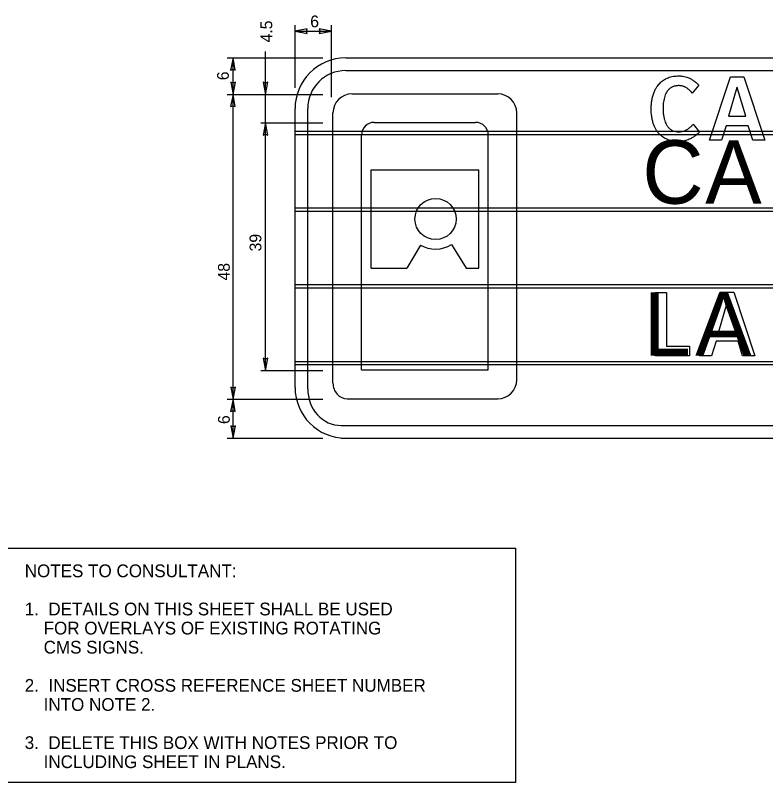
# Model space of a CAD drawing. Extents: x 319706 to 320346, y 1621790 to 1622121.
# Drawn here: x 319856.4 to 319945.5, y 1621813.2 to 1621904.4 of the extents above; entities that cross this region are included whole.
import ezdxf

# ---------------------------------------------------------------- set-up
doc = ezdxf.new("R2010")
doc.units = 0
for name, color, linetype in [('1', 7, 'Continuous'), ('52', 7, 'Continuous'), ('GSBWFill', 7, 'Continuous'), ('GSColorFill', 7, 'Continuous'), ('GSOutline', 7, 'Continuous'), ('SignPanel', 7, 'Continuous'), ('TextAlert', 7, 'Continuous')]:
    doc.layers.add(name, color=color, linetype=linetype)

msp = doc.modelspace()

# ---------------------------------------------------------------- linework, layer by layer
at = {"layer": '1'}
for p, q in [((319889.623, 1621895.788), (319889.623, 1621903.248)), ((319893.952, 1621894.663), (319893.952, 1621903.248)), ((319889.623, 1621902.519), (319893.952, 1621902.519)), ((319886.119, 1621895.01), (319886.119, 1621900.114)), ((319881.557, 1621899.343), (319892.941, 1621899.343)), ((319882.254, 1621895.01), (319882.254, 1621899.343)), ((319881.557, 1621895.01), (319892.941, 1621895.01)), ((319882.254, 1621858.786), (319882.254, 1621895.01)), ((319886.119, 1621891.622), (319886.119, 1621895.01)), ((319885.56, 1621891.622), (319892.941, 1621891.622)), ((319886.119, 1621862.212), (319886.119, 1621891.622)), ((319885.56, 1621862.212), (319892.941, 1621862.212)), ((319881.557, 1621858.786), (319892.941, 1621858.786)), ((319882.254, 1621854.168), (319882.254, 1621858.786)), ((319881.557, 1621854.168), (319892.941, 1621854.168))]:
    msp.add_line(p, q, dxfattribs=at)
at = {"layer": '52'}
for p, q in [((319891.073, 1621902.789), (319889.623, 1621902.519)), ((319889.623, 1621902.519), (319891.073, 1621902.239)), ((319890.963, 1621902.519), (319891.073, 1621902.789)), ((319891.073, 1621902.239), (319890.963, 1621902.519)), ((319893.952, 1621902.519), (319892.502, 1621902.799)), ((319892.502, 1621902.799), (319892.612, 1621902.519)), ((319892.612, 1621902.519), (319892.502, 1621902.249)), ((319892.502, 1621902.249), (319893.952, 1621902.519)), ((319882.254, 1621899.343), (319881.974, 1621897.893)), ((319882.524, 1621897.893), (319882.254, 1621899.343)), ((319881.974, 1621897.893), (319882.254, 1621898.003)), ((319882.254, 1621898.003), (319882.524, 1621897.893)), ((319882.254, 1621896.35), (319881.984, 1621896.46)), ((319881.984, 1621896.46), (319882.254, 1621895.01)), ((319882.254, 1621895.01), (319882.534, 1621896.46)), ((319882.534, 1621896.46), (319882.254, 1621896.35)), ((319886.119, 1621896.35), (319885.849, 1621896.46)), ((319885.849, 1621896.46), (319886.119, 1621895.01)), ((319886.119, 1621895.01), (319886.399, 1621896.46)), ((319886.399, 1621896.46), (319886.119, 1621896.35)), ((319882.254, 1621895.01), (319881.974, 1621893.56)), ((319882.524, 1621893.56), (319882.254, 1621895.01)), ((319881.974, 1621893.56), (319882.254, 1621893.67)), ((319882.254, 1621893.67), (319882.524, 1621893.56)), ((319886.119, 1621891.622), (319885.839, 1621890.172)), ((319886.389, 1621890.172), (319886.119, 1621891.622)), ((319885.839, 1621890.172), (319886.119, 1621890.282)), ((319886.119, 1621890.282), (319886.389, 1621890.172)), ((319886.119, 1621863.552), (319885.849, 1621863.662)), ((319885.849, 1621863.662), (319886.119, 1621862.212)), ((319886.119, 1621862.212), (319886.399, 1621863.662)), ((319886.399, 1621863.662), (319886.119, 1621863.552)), ((319882.254, 1621860.126), (319881.984, 1621860.236)), ((319881.984, 1621860.236), (319882.254, 1621858.786)), ((319882.254, 1621858.786), (319882.534, 1621860.236)), ((319882.534, 1621860.236), (319882.254, 1621860.126)), ((319882.254, 1621858.786), (319881.974, 1621857.336)), ((319882.524, 1621857.336), (319882.254, 1621858.786)), ((319881.974, 1621857.336), (319882.254, 1621857.446)), ((319882.254, 1621857.446), (319882.524, 1621857.336)), ((319882.254, 1621855.508), (319881.984, 1621855.618)), ((319881.984, 1621855.618), (319882.254, 1621854.168)), ((319882.254, 1621854.168), (319882.534, 1621855.618)), ((319882.534, 1621855.618), (319882.254, 1621855.508))]:
    msp.add_line(p, q, dxfattribs=at)
at = {"layer": 'GSOutline'}
for points in [[(319943.976, 1621889.554), (319943.426, 1621891.274), (319940.823, 1621891.274), (319940.273, 1621889.554), (319938.859, 1621889.554), (319941.327, 1621897.102), (319942.915, 1621897.102), (319945.436, 1621889.554), (319943.976, 1621889.554)], [(319937.595, 1621896.095), (319936.79, 1621895.162)], [(319942.139, 1621895.821), (319942.102, 1621895.823), (319941.094, 1621892.409), (319943.148, 1621892.409), (319942.139, 1621895.821)], [(319936.927, 1621891.465), (319937.649, 1621890.525)], [(319932.402, 1621863.954), (319932.402, 1621871.484), (319933.756, 1621871.484), (319933.756, 1621865.107), (319936.455, 1621865.107), (319936.455, 1621863.954), (319932.402, 1621863.954)], [(319942.784, 1621863.954), (319942.234, 1621865.674), (319939.631, 1621865.674), (319939.081, 1621863.954), (319937.667, 1621863.954), (319940.135, 1621871.502), (319941.722, 1621871.502), (319944.243, 1621863.954), (319942.784, 1621863.954)], [(319940.947, 1621870.221), (319940.91, 1621870.223), (319939.901, 1621866.809), (319941.956, 1621866.809), (319940.947, 1621870.221)]]:
    msp.add_lwpolyline(points, dxfattribs=at)
for points in [[(319931.922, 1621893.333), (319931.925, 1621893.462), (319931.931, 1621893.84), (319931.997, 1621894.338), (319932.109, 1621894.815), (319932.25, 1621895.261), (319932.447, 1621895.677), (319932.665, 1621896.004), (319932.835, 1621896.22), (319933.023, 1621896.419), (319933.276, 1621896.632), (319933.508, 1621896.784), (319933.705, 1621896.892), (319933.915, 1621896.991), (319934.199, 1621897.09), (319934.564, 1621897.167), (319934.888, 1621897.199), (319935.088, 1621897.202), (319935.157, 1621897.203)], [(319935.157, 1621897.203), (319935.218, 1621897.202), (319935.395, 1621897.2), (319935.683, 1621897.171), (319936.014, 1621897.103), (319936.274, 1621897.016), (319936.521, 1621896.907), (319936.868, 1621896.717), (319937.246, 1621896.435), (319937.504, 1621896.184), (319937.595, 1621896.095)], [(319935.188, 1621896.05), (319935.15, 1621896.05), (319935.039, 1621896.048), (319934.859, 1621896.029), (319934.654, 1621895.983), (319934.495, 1621895.925), (319934.376, 1621895.867), (319934.263, 1621895.802), (319934.13, 1621895.707), (319933.984, 1621895.572), (319933.875, 1621895.443), (319933.796, 1621895.331), (319933.658, 1621895.111), (319933.537, 1621894.823), (319933.444, 1621894.473), (319933.375, 1621894.115), (319933.336, 1621893.732), (319933.333, 1621893.436), (319933.331, 1621893.333)], [(319936.79, 1621895.162), (319936.729, 1621895.231), (319936.611, 1621895.364), (319936.456, 1621895.517), (319936.303, 1621895.651), (319936.179, 1621895.744), (319936.05, 1621895.825), (319935.921, 1621895.896), (319935.786, 1621895.952), (319935.647, 1621895.995), (319935.5, 1621896.028), (319935.347, 1621896.047), (319935.229, 1621896.049), (319935.188, 1621896.05)], [(319935.151, 1621889.426), (319935.014, 1621889.429), (319934.812, 1621889.434), (319934.488, 1621889.473), (319934.186, 1621889.532), (319933.902, 1621889.625), (319933.691, 1621889.718), (319933.493, 1621889.82), (319933.261, 1621889.966), (319933.008, 1621890.172), (319932.82, 1621890.367), (319932.685, 1621890.536), (319932.557, 1621890.716), (319932.383, 1621891.006), (319932.221, 1621891.378), (319932.101, 1621891.778), (319931.993, 1621892.274), (319931.931, 1621892.796), (319931.924, 1621893.196), (319931.922, 1621893.333)], [(319933.331, 1621893.333), (319933.335, 1621893.161), (319933.344, 1621892.822), (319933.401, 1621892.404), (319933.487, 1621892.007), (319933.588, 1621891.709), (319933.706, 1621891.468), (319933.799, 1621891.309), (319933.903, 1621891.162), (319934.047, 1621891.004), (319934.182, 1621890.888), (319934.297, 1621890.806), (319934.421, 1621890.731), (319934.592, 1621890.656), (319934.818, 1621890.597), (319935.02, 1621890.573), (319935.146, 1621890.571), (319935.189, 1621890.57)], [(319935.189, 1621890.57), (319935.231, 1621890.571), (319935.355, 1621890.573), (319935.556, 1621890.596), (319935.786, 1621890.651), (319935.967, 1621890.721), (319936.141, 1621890.81), (319936.391, 1621890.967), (319936.666, 1621891.195), (319936.858, 1621891.394), (319936.927, 1621891.465)], [(319937.649, 1621890.525), (319937.562, 1621890.44), (319937.308, 1621890.195), (319936.925, 1621889.922), (319936.57, 1621889.733), (319936.309, 1621889.621), (319936.036, 1621889.531), (319935.693, 1621889.46), (319935.395, 1621889.43), (319935.213, 1621889.427), (319935.151, 1621889.426)]]:
    msp.add_open_spline(points, degree=3, dxfattribs=at)
at = {"layer": 'SignPanel'}
for p, q in [((319895.646, 1621899.343), (319992.019, 1621899.343)), ((319895.646, 1621897.838), (319992.019, 1621897.838)), ((319896.387, 1621895.073), (319913.704, 1621895.073)), ((319889.623, 1621860.191), (319889.623, 1621893.319)), ((319891.129, 1621860.033), (319891.129, 1621893.319)), ((319894.127, 1621860.719), (319894.127, 1621892.816)), ((319915.961, 1621861.109), (319915.961, 1621892.816)), ((319899.021, 1621891.685), (319911.068, 1621891.685)), ((319889.623, 1621890.636), (319998.043, 1621890.636)), ((319889.623, 1621890.26), (319998.043, 1621890.26)), ((319897.515, 1621862.275), (319897.515, 1621890.179)), ((319912.574, 1621862.275), (319912.574, 1621890.179)), ((319898.646, 1621874.369), (319898.646, 1621886.039)), ((319898.646, 1621886.039), (319911.444, 1621886.039)), ((319911.444, 1621874.379), (319911.444, 1621886.039)), ((319889.623, 1621881.527), (319998.043, 1621881.527)), ((319889.623, 1621881.151), (319998.043, 1621881.151)), ((319904.508, 1621877.116), (319902.904, 1621874.369)), ((319908.202, 1621877.167), (319909.939, 1621874.379)), ((319898.646, 1621874.369), (319902.904, 1621874.369)), ((319909.939, 1621874.379), (319911.444, 1621874.379)), ((319889.623, 1621872.417), (319998.043, 1621872.417)), ((319889.623, 1621872.011), (319998.043, 1621872.011)), ((319889.623, 1621863.277), (319998.043, 1621863.277)), ((319889.623, 1621862.902), (319998.043, 1621862.902)), ((319897.515, 1621862.275), (319912.574, 1621862.275)), ((319895.821, 1621858.849), (319913.704, 1621858.849)), ((319895.082, 1621855.673), (319992.019, 1621855.673)), ((319895.113, 1621854.168), (319992.019, 1621854.168))]:
    msp.add_line(p, q, dxfattribs=at)
msp.add_circle((319906.312, 1621880.205), 2.447, dxfattribs=at)
for centre, radius, start, end in [((319895.646, 1621893.319), 6.023, 90, 180), ((319895.646, 1621893.319), 4.517, 90, 180), ((319896.386, 1621892.816), 2.259, 90, 180), ((319913.703, 1621892.816), 2.259, 0, 90), ((319899.021, 1621890.181), 1.506, 90, 180), ((319911.068, 1621890.181), 1.506, 0, 90), ((319906.312, 1621880.205), 3.576, 239.72059, 301.90487), ((319913.703, 1621861.109), 2.259, 270, 360), ((319895.646, 1621860.191), 6.023, 180, 270)]:
    msp.add_arc(centre, radius, start, end, dxfattribs=at)
for centre, major_axis in [((319895.821, 1621860.719), (0, 1.868)), ((319895.081, 1621860.033), (0, 4.36))]:
    msp.add_ellipse(centre, major_axis=major_axis, ratio=0.906668, start_param=1.570796, end_param=3.141593, dxfattribs=at)
at = {"layer": 'TextAlert'}
msp.add_lwpolyline([(319855.135, 1621841.105), (319915.823, 1621841.105), (319915.823, 1621813.24), (319855.135, 1621813.24)], close=True, dxfattribs=at)

# ---------------------------------------------------------------- texts
at = {"layer": '1'}
msp.add_text('6', height=1.4, dxfattribs=at).set_placement((319891.425, 1621902.981))
for s, p in [('4.5', (319886.914, 1621901.181)), ('6', (319881.757, 1621896.693)), ('39', (319885.622, 1621876.353)), ('48', (319881.871, 1621872.896)), ('6', (319881.871, 1621855.845))]:
    msp.add_text(s, height=1.4, rotation=90, dxfattribs=at).set_placement(p)
at = {"layer": 'GSBWFill'}
for s, p in [('C', (319930.87, 1621882.025)), ('A', (319938.332, 1621882.025)), ('L', (319931.048, 1621863.954)), ('A', (319937.14, 1621863.954))]:
    msp.add_text(s, height=7.53, dxfattribs=at).set_placement(p)
at = {"layer": 'GSColorFill'}
for s, p in [('C', (319930.87, 1621882.025)), ('A', (319938.332, 1621882.025)), ('L', (319931.048, 1621863.954)), ('A', (319937.14, 1621863.954))]:
    msp.add_text(s, height=7.53, dxfattribs=at).set_placement(p)
at = {"layer": 'TextAlert'}
for s, p in [('NOTES TO CONSULTANT:', (319857.515, 1621837.649)), ('1.  DETAILS ON THIS SHEET SHALL BE USED', (319857.515, 1621833.113)), ('    FOR OVERLAYS OF EXISTING ROTATING', (319857.515, 1621830.845)), ('    CMS SIGNS.', (319857.515, 1621828.577)), ('2.  INSERT CROSS REFERENCE SHEET NUMBER', (319857.515, 1621824.041)), ('    INTO NOTE 2.', (319857.515, 1621821.773)), ('3.  DELETE THIS BOX WITH NOTES PRIOR TO', (319857.515, 1621817.237)), ('    INCLUDING SHEET IN PLANS.', (319857.515, 1621814.969))]:
    msp.add_text(s, height=1.512, dxfattribs=at).set_placement(p)

doc.saveas('drawing.dxf')
